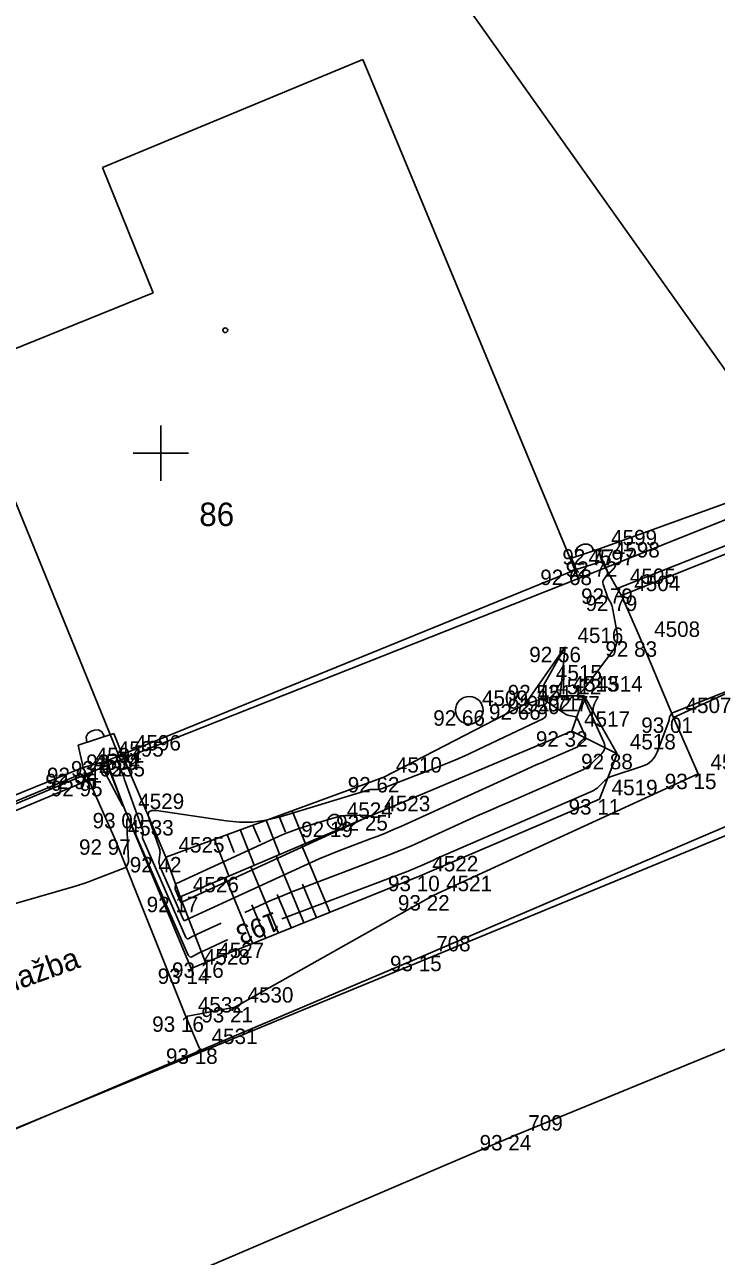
# Model space of a CAD drawing. Extents: x -711081 to -709338, y -1025122 to -1024092.
# Drawn here: x -709877.47 to -709864.93, y -1024564.56 to -1024542.23 of the extents above; entities that cross this region are included whole.
import ezdxf

# ---------------------------------------------------------------- set-up
doc = ezdxf.new("R2010")
doc.units = 0
for name, color, linetype in [('Ex_Contour Labels', 7, 'Continuous'), ('Ex_Major Contours', 7, 'Continuous'), ('Ex_Minor Contours', 7, 'Continuous'), ('Z_betonova_konstrukce', 7, 'Continuous'), ('Z_body', 7, 'Continuous'), ('Z_body_cisla', 7, 'Continuous'), ('Z_body_vysky_redukovane', 7, 'Continuous'), ('Z_budova', 7, 'Continuous'), ('Z_hektometricka_sit', 7, 'Continuous'), ('Z_hrany_paty', 7, 'Continuous'), ('Z_katastr_cisla_stavebni', 7, 'Continuous'), ('Z_katastr_hranice', 7, 'Continuous'), ('Z_katastr_vnitrni_kresba', 7, 'Continuous'), ('Z_katastr_znacky_budov', 7, 'Continuous'), ('Z_komunikace', 7, 'Continuous'), ('Z_komunikace_osa', 7, 'Continuous'), ('Z_ploty', 7, 'Continuous'), ('Z_ploty_znacky', 7, 'Continuous'), ('Z_popisy', 7, 'Continuous'), ('Z_rozhranni', 7, 'Continuous'), ('Z_site_vodovod_znaky', 7, 'Continuous'), ('Z_technicke_srafy', 7, 'Continuous'), ('Z_vstupy', 7, 'Continuous'), ('Z_zelen_jednotliva', 7, 'Continuous'), ('Z_zlabek', 7, 'Continuous')]:
    doc.layers.add(name, color=color, linetype=linetype)

# ---------------------------------------------------------------- blocks, each defined once
blk = doc.blocks.new('POINT_DISPLAY')
blk.add_line((0, 0), (0, 0))
blk = doc.blocks.new('Z10001')
blk.add_circle((0, 0), 0.25)
blk = doc.blocks.new('Z216')
for p, q in [((-0.17, 0), (-0.15, 0.1)), ((-0.15, 0.1), (-0.1, 0.15)), ((-0.1, 0.15), (-0.03, 0.17)), ((-0.03, 0.17), (0.03, 0.17)), ((0.03, 0.17), (0.1, 0.15)), ((0.1, 0.15), (0.15, 0.1)), ((0.15, 0.1), (0.17, 0))]:
    blk.add_line(p, q)
blk = doc.blocks.new('Z614')
for p, q in [((-0.13, 0.03), (-0.1, 0.08)), ((-0.13, -0.03), (-0.13, 0.03)), ((-0.1, 0.08), (-0.08, 0.1)), ((-0.08, 0.1), (-0.03, 0.13)), ((-0.03, 0.13), (0.03, 0.13)), ((0.03, 0.13), (0.08, 0.1)), ((0.08, 0.1), (0.1, 0.08)), ((0.1, 0.08), (0.13, 0.03)), ((0.13, 0.03), (0.13, -0.03)), ((-0.1, -0.08), (-0.13, -0.03)), ((-0.08, -0.1), (-0.1, -0.08)), ((-0.03, -0.13), (-0.08, -0.1)), ((0.03, -0.13), (-0.03, -0.13)), ((0.08, -0.1), (0.03, -0.13)), ((0.1, -0.08), (0.08, -0.1)), ((0.13, -0.03), (0.1, -0.08))]:
    blk.add_line(p, q)

msp = doc.modelspace()

# ---------------------------------------------------------------- linework, layer by layer
at = {"layer": 'Ex_Major Contours'}
for points in [[(-709864.538, -1024554.234), (-709865.726, -1024554.707), (-709865.734, -1024554.711), (-709865.74, -1024554.715), (-709865.746, -1024554.721), (-709865.751, -1024554.728), (-709865.769, -1024554.759), (-709865.773, -1024554.767), (-709865.776, -1024554.774), (-709865.779, -1024554.782), (-709865.78, -1024554.791), (-709865.786, -1024554.824), (-709865.787, -1024554.832), (-709865.789, -1024554.841), (-709865.792, -1024554.849), (-709865.794, -1024554.857), (-709866.005, -1024555.418), (-709866.048, -1024555.506), (-709866.107, -1024555.578), (-709866.182, -1024555.634), (-709866.272, -1024555.674), (-709866.822, -1024555.853), (-709866.859, -1024555.868), (-709866.892, -1024555.886), (-709866.924, -1024555.907), (-709866.953, -1024555.933), (-709867.064, -1024556.044), (-709867.093, -1024556.07), (-709867.124, -1024556.093), (-709867.157, -1024556.113), (-709867.192, -1024556.13), (-709869.833, -1024557.274), (-709869.89, -1024557.299), (-709869.947, -1024557.325), (-709870.004, -1024557.35), (-709870.061, -1024557.376), (-709870.289, -1024557.479), (-709870.346, -1024557.504), (-709870.403, -1024557.529), (-709870.461, -1024557.552), (-709870.519, -1024557.575), (-709872.81, -1024558.44)], [(-709876.103, -1024555.61), (-709875.746, -1024556.296), (-709875.701, -1024556.379), (-709875.681, -1024556.405), (-709875.687, -1024556.373), (-709875.719, -1024556.284), (-709875.986, -1024555.574)], [(-709873.789, -1024558.82), (-709873.81, -1024558.83), (-709874.209, -1024559.012), (-709874.237, -1024559.025), (-709874.264, -1024559.039), (-709874.291, -1024559.052), (-709874.318, -1024559.066), (-709874.425, -1024559.124), (-709874.45, -1024559.133), (-709874.472, -1024559.131), (-709874.489, -1024559.119), (-709874.503, -1024559.097), (-709875.54, -1024556.725), (-709875.579, -1024556.649), (-709875.605, -1024556.627), (-709875.618, -1024556.658), (-709875.619, -1024556.743), (-709875.588, -1024557.387), (-709875.588, -1024557.4), (-709875.589, -1024557.412), (-709875.592, -1024557.425), (-709875.597, -1024557.436), (-709875.618, -1024557.483), (-709875.624, -1024557.494), (-709875.631, -1024557.503), (-709875.641, -1024557.511), (-709875.652, -1024557.516), (-709876.2, -1024557.73), (-709876.296, -1024557.766), (-709876.393, -1024557.8), (-709876.49, -1024557.832), (-709876.588, -1024557.861), (-709880.135, -1024558.882)]]:
    msp.add_lwpolyline(points, dxfattribs=at)
at = {"layer": 'Ex_Minor Contours'}
for points in [[(-709873.477, -1024558.324), (-709873.217, -1024558.205), (-709873.023, -1024558.117), (-709872.827, -1024558.034), (-709872.629, -1024557.953), (-709872.43, -1024557.876), (-709871.067, -1024557.362), (-709870.863, -1024557.283), (-709870.661, -1024557.201), (-709870.46, -1024557.115), (-709870.26, -1024557.026), (-709869.464, -1024556.665), (-709869.265, -1024556.575), (-709869.065, -1024556.486), (-709868.865, -1024556.398), (-709868.665, -1024556.311), (-709867.393, -1024555.76), (-709867.337, -1024555.732), (-709867.284, -1024555.7), (-709867.235, -1024555.663), (-709867.188, -1024555.621), (-709867.01, -1024555.443), (-709866.974, -1024555.398), (-709866.956, -1024555.348), (-709866.955, -1024555.296), (-709866.972, -1024555.24), (-709867.326, -1024554.46), (-709867.334, -1024554.445), (-709867.345, -1024554.434), (-709867.358, -1024554.426), (-709867.373, -1024554.421), (-709867.44, -1024554.407), (-709867.453, -1024554.403), (-709867.458, -1024554.397), (-709867.456, -1024554.389), (-709867.446, -1024554.379), (-709867.39, -1024554.336), (-709867.377, -1024554.325), (-709867.364, -1024554.314), (-709867.352, -1024554.301), (-709867.341, -1024554.287), (-709866.806, -1024553.581), (-709866.761, -1024553.508), (-709866.734, -1024553.431), (-709866.724, -1024553.35), (-709866.731, -1024553.265), (-709866.822, -1024552.773), (-709866.825, -1024552.758), (-709866.83, -1024552.743), (-709866.836, -1024552.729), (-709866.844, -1024552.715), (-709866.877, -1024552.661), (-709866.885, -1024552.648), (-709866.892, -1024552.634), (-709866.898, -1024552.619), (-709866.904, -1024552.605), (-709866.984, -1024552.371), (-709866.989, -1024552.349), (-709866.988, -1024552.328), (-709866.983, -1024552.307), (-709866.972, -1024552.287), (-709866.917, -1024552.209), (-709866.907, -1024552.189), (-709866.902, -1024552.169), (-709866.903, -1024552.148), (-709866.91, -1024552.127), (-709867.046, -1024551.828)], [(-709875.812, -1024555.505), (-709875.707, -1024555.781), (-709875.69, -1024555.828), (-709875.673, -1024555.874), (-709875.656, -1024555.92), (-709875.64, -1024555.967), (-709875.329, -1024556.838), (-709875.325, -1024556.851), (-709875.323, -1024556.865), (-709875.322, -1024556.879), (-709875.323, -1024556.893), (-709875.331, -1024556.95), (-709875.332, -1024556.964), (-709875.331, -1024556.977), (-709875.328, -1024556.991), (-709875.323, -1024557.004), (-709874.547, -1024558.778), (-709874.538, -1024558.794), (-709874.525, -1024558.803), (-709874.51, -1024558.804), (-709874.493, -1024558.797), (-709874.418, -1024558.757), (-709874.399, -1024558.747), (-709874.38, -1024558.738), (-709874.361, -1024558.728), (-709874.342, -1024558.719), (-709873.906, -1024558.52)]]:
    msp.add_lwpolyline(points, dxfattribs=at)
for points in [[(-709871.23, -1024556.103), (-709871.208, -1024556.099), (-709871.186, -1024556.097), (-709871.163, -1024556.095), (-709871.073, -1024556.094), (-709871.051, -1024556.093), (-709871.029, -1024556.09), (-709871.007, -1024556.085), (-709870.986, -1024556.077), (-709869.954, -1024555.677), (-709869.776, -1024555.606), (-709869.599, -1024555.532), (-709869.423, -1024555.454), (-709869.249, -1024555.373), (-709868.077, -1024554.817), (-709868.044, -1024554.796), (-709868.024, -1024554.769), (-709868.016, -1024554.736), (-709868.02, -1024554.698), (-709868.06, -1024554.533), (-709868.064, -1024554.499), (-709868.057, -1024554.483), (-709868.039, -1024554.482), (-709868.01, -1024554.498), (-709867.686, -1024554.718), (-709867.666, -1024554.73), (-709867.645, -1024554.74), (-709867.623, -1024554.748), (-709867.601, -1024554.754), (-709867.508, -1024554.774), (-709867.487, -1024554.781), (-709867.469, -1024554.792), (-709867.454, -1024554.808), (-709867.443, -1024554.827), (-709867.308, -1024555.124), (-709867.301, -1024555.147), (-709867.301, -1024555.169), (-709867.309, -1024555.19), (-709867.324, -1024555.209), (-709867.399, -1024555.283), (-709867.418, -1024555.301), (-709867.439, -1024555.316), (-709867.461, -1024555.33), (-709867.484, -1024555.341), (-709867.997, -1024555.564), (-709868.091, -1024555.604), (-709868.184, -1024555.645), (-709868.277, -1024555.687), (-709868.37, -1024555.729), (-709870.65, -1024556.764), (-709870.782, -1024556.822), (-709870.916, -1024556.879), (-709871.05, -1024556.934), (-709871.186, -1024556.986), (-709871.728, -1024557.191), (-709871.864, -1024557.243), (-709871.998, -1024557.298), (-709872.131, -1024557.355), (-709872.263, -1024557.414), (-709874.475, -1024558.427), (-709874.486, -1024558.432), (-709874.497, -1024558.437), (-709874.507, -1024558.442), (-709874.518, -1024558.448), (-709874.561, -1024558.471), (-709874.571, -1024558.474), (-709874.579, -1024558.474), (-709874.586, -1024558.469), (-709874.592, -1024558.46), (-709875.017, -1024557.488), (-709875.026, -1024557.462), (-709875.032, -1024557.435), (-709875.034, -1024557.407), (-709875.032, -1024557.379), (-709875.017, -1024557.266), (-709875.015, -1024557.238), (-709875.016, -1024557.21), (-709875.021, -1024557.183), (-709875.028, -1024557.156), (-709875.214, -1024556.636), (-709875.231, -1024556.554), (-709875.215, -1024556.5), (-709875.165, -1024556.474), (-709875.081, -1024556.475), (-709873.818, -1024556.666), (-709873.575, -1024556.69), (-709873.334, -1024556.686), (-709873.095, -1024556.655), (-709872.858, -1024556.597), (-709871.251, -1024556.109)], [(-709871.792, -1024556.59), (-709871.724, -1024556.577), (-709871.656, -1024556.569), (-709871.587, -1024556.565), (-709871.309, -1024556.562), (-709871.256, -1024556.565), (-709871.236, -1024556.575), (-709871.25, -1024556.593), (-709871.296, -1024556.618), (-709874.607, -1024558.134), (-709874.618, -1024558.139), (-709874.628, -1024558.144), (-709874.631, -1024558.145), (-709874.633, -1024558.145), (-709874.635, -1024558.144), (-709874.636, -1024558.142), (-709874.736, -1024557.913), (-709874.74, -1024557.903), (-709874.742, -1024557.893), (-709874.742, -1024557.883), (-709874.742, -1024557.873), (-709874.736, -1024557.831), (-709874.734, -1024557.821), (-709874.729, -1024557.813), (-709874.723, -1024557.806), (-709874.714, -1024557.801), (-709872.867, -1024556.948), (-709872.757, -1024556.899), (-709872.645, -1024556.855), (-709872.532, -1024556.814), (-709872.418, -1024556.777), (-709871.859, -1024556.607)]]:
    msp.add_lwpolyline(points, close=True, dxfattribs=at)
at = {"layer": 'Z_betonova_konstrukce'}
for p, q in [((-709875.7, -1024555.46), (-709874.91, -1024557.32)), ((-709876, -1024555.58), (-709875.63, -1024556.52)), ((-709874.45, -1024559.34), (-709875.63, -1024556.52)), ((-709874.91, -1024557.32), (-709874.65, -1024558.04)), ((-709874.65, -1024558.04), (-709874.19, -1024559.23)), ((-709874.19, -1024559.23), (-709874.45, -1024559.34))]:
    msp.add_line(p, q, dxfattribs=at)
at = {"layer": 'Z_budova'}
for p, q in [((-709875.7, -1024555.46), (-709867.47, -1024552.11)), ((-709867.56, -1024551.9), (-709867.47, -1024552.11)), ((-709875.85, -1024555.08), (-709875.7, -1024555.46))]:
    msp.add_line(p, q, dxfattribs=at)
at = {"layer": 'Z_hektometricka_sit'}
for p, q in [((-709875, -1024549.5), (-709875, -1024550.5)), ((-709875.5, -1024550), (-709874.5, -1024550))]:
    msp.add_line(p, q, dxfattribs=at)
at = {"layer": 'Z_hrany_paty'}
for p, q in [((-709868.4, -1024554.55), (-709867.67, -1024553.51)), ((-709868.06, -1024554.2), (-709867.67, -1024553.51)), ((-709867.67, -1024553.51), (-709867.76, -1024554.4)), ((-709868.06, -1024554.2), (-709868.08, -1024554.45)), ((-709870.96, -1024555.87), (-709868.4, -1024554.55)), ((-709868.4, -1024554.55), (-709868.08, -1024554.45)), ((-709868.08, -1024554.45), (-709867.76, -1024554.4)), ((-709867.76, -1024554.4), (-709867.33, -1024554.4)), ((-709867.55, -1024555.04), (-709867.33, -1024554.4)), ((-709867.33, -1024554.4), (-709866.73, -1024555.45)), ((-709867.55, -1024555.04), (-709871.17, -1024556.56)), ((-709867.55, -1024555.04), (-709866.73, -1024555.45)), ((-709866.73, -1024555.45), (-709867.05, -1024556.27)), ((-709870.96, -1024555.87), (-709874.91, -1024557.32)), ((-709867.05, -1024556.27), (-709870.3, -1024557.66)), ((-709871.17, -1024556.56), (-709874.65, -1024558.04)), ((-709870.3, -1024557.66), (-709874.19, -1024559.23))]:
    msp.add_line(p, q, dxfattribs=at)
at = {"layer": 'Z_katastr_hranice'}
for p, q in [((-709863.27, -1024550.61), (-709872.34, -1024537.83)), ((-709875.73, -1024555.56), (-709878.61, -1024548.5)), ((-709867.43, -1024552.27), (-709863.27, -1024550.61)), ((-709875.73, -1024555.56), (-709867.43, -1024552.27)), ((-709884.99, -1024559.44), (-709875.73, -1024555.56))]:
    msp.add_line(p, q, dxfattribs=at)
at = {"layer": 'Z_katastr_vnitrni_kresba'}
for p, q in [((-709879.87, -1024563.16), (-709829.33, -1024542.31)), ((-709876.06, -1024544.82), (-709871.34, -1024542.86)), ((-709871.34, -1024542.86), (-709867.43, -1024552.27)), ((-709875.14, -1024547.09), (-709876.06, -1024544.82)), ((-709878.61, -1024548.5), (-709875.14, -1024547.09))]:
    msp.add_line(p, q, dxfattribs=at)
at = {"layer": 'Z_katastr_znacky_budov'}
msp.add_circle((-709873.832, -1024547.77), 0.0437, dxfattribs=at)
at = {"layer": 'Z_komunikace'}
for p, q in [((-709870.24, -1024559.11), (-709860.85, -1024555.09)), ((-709886.5, -1024566.01), (-709870.24, -1024559.11))]:
    msp.add_line(p, q, dxfattribs=at)
at = {"layer": 'Z_komunikace_osa'}
for p, q in [((-709868.57, -1024562.36), (-709852.88, -1024555.91)), ((-709884.59, -1024569.21), (-709868.57, -1024562.36))]:
    msp.add_line(p, q, dxfattribs=at)
at = {"layer": 'Z_ploty'}
for p, q in [((-709867.56, -1024551.9), (-709867.07, -1024551.74)), ((-709867.01, -1024551.96), (-709867.07, -1024551.74)), ((-709867.47, -1024552.11), (-709867.01, -1024551.96)), ((-709876.5, -1024555.29), (-709875.85, -1024555.08)), ((-709876.5, -1024555.29), (-709876.41, -1024555.7)), ((-709876, -1024555.58), (-709875.7, -1024555.46)), ((-709876.41, -1024555.7), (-709876, -1024555.58))]:
    msp.add_line(p, q, dxfattribs=at)
at = {"layer": 'Z_rozhranni'}
for p, q in [((-709867.01, -1024551.96), (-709866.73, -1024552.45)), ((-709866.73, -1024552.45), (-709866.65, -1024552.58)), ((-709866.65, -1024552.58), (-709866.29, -1024553.41)), ((-709865.71, -1024554.79), (-709866.29, -1024553.41)), ((-709862.69, -1024553.41), (-709865.71, -1024554.79)), ((-709865.71, -1024554.79), (-709865.26, -1024555.81)), ((-709876.41, -1024555.7), (-709875.83, -1024557)), ((-709865.26, -1024555.81), (-709870.05, -1024558.01)), ((-709874.55, -1024560.21), (-709875.83, -1024557)), ((-709870.05, -1024558.01), (-709873.66, -1024560.04)), ((-709874.55, -1024560.21), (-709873.66, -1024560.04)), ((-709874.3, -1024560.79), (-709874.55, -1024560.21))]:
    msp.add_line(p, q, dxfattribs=at)
at = {"layer": 'Z_technicke_srafy'}
for p, q in [((-709872.86, -1024556.57), (-709872.74, -1024556.87)), ((-709872.62, -1024556.48), (-709872.38, -1024557.08)), ((-709873.33, -1024556.74), (-709873.2, -1024557.05)), ((-709873.09, -1024556.65), (-709872.85, -1024557.27)), ((-709874.03, -1024557), (-709873.77, -1024557.66)), ((-709873.8, -1024556.91), (-709873.67, -1024557.24)), ((-709873.56, -1024556.82), (-709873.31, -1024557.47)), ((-709871.94, -1024558.32), (-709872.45, -1024557.1)), ((-709872.41, -1024558.51), (-709872.91, -1024557.3)), ((-709873.34, -1024558.88), (-709873.83, -1024557.69)), ((-709872.87, -1024558.7), (-709873.37, -1024557.5)), ((-709872.18, -1024558.42), (-709872.43, -1024557.81)), ((-709872.64, -1024558.6), (-709872.89, -1024558)), ((-709873.1, -1024558.79), (-709873.35, -1024558.19))]:
    msp.add_line(p, q, dxfattribs=at)
at = {"layer": 'Z_vstupy'}
for p, q in [((-709867.07, -1024551.74), (-709863.51, -1024550.45)), ((-709879.79, -1024557.06), (-709876.41, -1024555.7))]:
    msp.add_line(p, q, dxfattribs=at)
at = {"layer": 'Z_zlabek'}
for p, q in [((-709863, -1024550.98), (-709866.73, -1024552.45)), ((-709862.93, -1024551.09), (-709866.65, -1024552.58)), ((-709881.23, -1024557.82), (-709876.44, -1024555.81)), ((-709876.44, -1024555.81), (-709876.34, -1024555.94)), ((-709876.34, -1024555.94), (-709880.74, -1024557.77))]:
    msp.add_line(p, q, dxfattribs=at)

# ---------------------------------------------------------------- block references
at = {"layer": 'Z_body'}
for p in [(-709867.07, -1024551.74), (-709867.47, -1024552.11), (-709867.01, -1024551.96), (-709866.73, -1024552.45), (-709866.65, -1024552.58), (-709866.29, -1024553.41), (-709867.67, -1024553.51), (-709868.06, -1024554.2), (-709868.4, -1024554.55), (-709868.08, -1024554.45), (-709867.76, -1024554.4), (-709867.33, -1024554.4), (-709869.41, -1024554.66), (-709865.71, -1024554.79), (-709867.55, -1024555.04), (-709875.7, -1024555.46), (-709866.73, -1024555.45), (-709876, -1024555.58), (-709876.44, -1024555.81), (-709876.41, -1024555.7), (-709870.96, -1024555.87), (-709865.26, -1024555.81), (-709876.34, -1024555.94), (-709867.05, -1024556.27), (-709875.63, -1024556.52), (-709871.17, -1024556.56), (-709871.85, -1024556.68), (-709875.83, -1024557), (-709874.91, -1024557.32), (-709870.3, -1024557.66), (-709874.65, -1024558.04), (-709870.05, -1024558.01), (-709874.19, -1024559.23), (-709870.24, -1024559.11), (-709874.45, -1024559.34), (-709873.66, -1024560.04), (-709874.55, -1024560.21), (-709874.3, -1024560.79), (-709868.57, -1024562.36)]:
    msp.add_blockref('POINT_DISPLAY', p, dxfattribs=at)
at = {"layer": 'Z_ploty_znacky'}
for p, rotation in [((-709867.31, -1024551.82), 18.1), ((-709876.18, -1024555.19), 18.200000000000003)]:
    msp.add_blockref('Z216', p, dxfattribs=dict(at, rotation=rotation))
at = {"layer": 'Z_site_vodovod_znaky'}
msp.add_blockref('Z614', (-709871.85, -1024556.68), dxfattribs=at)
at = {"layer": 'Z_zelen_jednotliva'}
msp.add_blockref('Z10001', (-709869.41, -1024554.66), dxfattribs=at)

# ---------------------------------------------------------------- texts
at = {"layer": 'Ex_Contour Labels'}
msp.add_text('193', height=0.35, rotation=201.233, dxfattribs=at).set_placement((-709872.942, -1024558.303))
at = {"layer": 'Z_body_cisla'}
for s, p in [('4599', (-709866.84, -1024551.67)), ('4598', (-709866.79, -1024551.89)), ('4597', (-709867.25, -1024552.03)), ('4505', (-709866.5, -1024552.37)), ('4504', (-709866.42, -1024552.5)), ('4516', (-709867.45, -1024553.44)), ('4508', (-709866.06, -1024553.33)), ('4515', (-709867.84, -1024554.12)), ('4512', (-709867.85, -1024554.37)), ('4513', (-709867.54, -1024554.32)), ('4514', (-709867.1, -1024554.32)), ('4509', (-709869.18, -1024554.58)), ('4511', (-709868.17, -1024554.48)), ('4507', (-709865.49, -1024554.71)), ('4517', (-709867.33, -1024554.96)), ('4595', (-709875.78, -1024555.5)), ('4596', (-709875.47, -1024555.39)), ('4518', (-709866.5, -1024555.37)), ('4534', (-709876.21, -1024555.74)), ('4594', (-709876.18, -1024555.62)), ('4520', (-709865.04, -1024555.74)), ('4535', (-709876.12, -1024555.86)), ('4510', (-709870.74, -1024555.79)), ('4519', (-709866.83, -1024556.2)), ('4529', (-709875.41, -1024556.45)), ('4524', (-709871.63, -1024556.61)), ('4523', (-709870.95, -1024556.49)), ('4533', (-709875.6, -1024556.93)), ('4525', (-709874.68, -1024557.24)), ('4522', (-709870.08, -1024557.58)), ('4526', (-709874.42, -1024557.96)), ('4521', (-709869.83, -1024557.94)), ('708', (-709870.01, -1024559.03)), ('4528', (-709874.22, -1024559.27)), ('4527', (-709873.96, -1024559.15)), ('4530', (-709873.43, -1024559.96)), ('4532', (-709874.33, -1024560.14)), ('4531', (-709874.08, -1024560.71)), ('709', (-709868.34, -1024562.28))]:
    msp.add_text(s, height=0.28, dxfattribs=at).set_placement(p)
at = {"layer": 'Z_body_vysky_redukovane'}
for s, p in [('92 77', (-709867.723, -1024552.02)), ('92 68', (-709868.123, -1024552.39)), ('92 72', (-709867.663, -1024552.24)), ('92 79', (-709867.383, -1024552.73)), ('92 79', (-709867.303, -1024552.86)), ('92 83', (-709866.943, -1024553.69)), ('92 56', (-709868.323, -1024553.79)), ('92 52', (-709868.713, -1024554.48)), ('92 66', (-709869.053, -1024554.83)), ('92 50', (-709868.71, -1024554.73)), ('92 71', (-709868.367, -1024554.68)), ('92 77', (-709867.983, -1024554.68)), ('92 66', (-709870.063, -1024554.94)), ('93 01', (-709866.293, -1024555.07)), ('92 32', (-709868.203, -1024555.32)), ('92 59', (-709876.353, -1024555.74)), ('92 88', (-709867.383, -1024555.73)), ('93 02', (-709876.63, -1024555.86)), ('92 95', (-709877.093, -1024556.09)), ('92 94', (-709877.063, -1024555.98)), ('92 62', (-709871.613, -1024556.15)), ('93 15', (-709865.867, -1024556.09)), ('92 95', (-709876.993, -1024556.22)), ('93 11', (-709867.61, -1024556.55)), ('93 00', (-709876.237, -1024556.8)), ('92 25', (-709871.823, -1024556.84)), ('92 19', (-709872.457, -1024556.96)), ('92 97', (-709876.483, -1024557.28)), ('92 42', (-709875.563, -1024557.6)), ('93 10', (-709870.883, -1024557.94)), ('92 17', (-709875.257, -1024558.32)), ('93 22', (-709870.703, -1024558.29)), ('93 16', (-709874.797, -1024559.51)), ('93 15', (-709870.847, -1024559.39)), ('93 14', (-709875.057, -1024559.62)), ('93 21', (-709874.267, -1024560.32)), ('93 16', (-709875.157, -1024560.49)), ('93 18', (-709874.907, -1024561.07)), ('93 24', (-709869.223, -1024562.64))]:
    msp.add_text(s, height=0.28, dxfattribs=at).set_placement(p)
at = {"layer": 'Z_katastr_cisla_stavebni'}
msp.add_text('86', height=0.425, dxfattribs=at).set_placement((-709874.303, -1024551.32))
at = {"layer": 'Z_popisy'}
msp.add_text('dlažba', height=0.4, rotation=19.8, dxfattribs=at).set_placement((-709877.92, -1024559.85))

doc.saveas('drawing.dxf')
